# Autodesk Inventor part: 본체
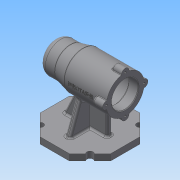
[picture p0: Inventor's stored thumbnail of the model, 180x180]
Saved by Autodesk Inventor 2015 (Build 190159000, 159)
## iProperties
Created: 2019-12
Part Number: 본체
Material: 일반
Document SubType Name: Modeling
Designer: user
Density: 1 g/cm^3
Appearance: 기본값
Mass: 268.496 g
Surface Area: 715.535 cm^2
Volume: 268.496 cm^3
Author: user
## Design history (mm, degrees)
sketch "스케치1"
  geometry: L1 (-56, 0)-(56, 0); L2 (56, 0)-(56, 21); L3 (56, 21)-(41, 21); L4 (41, 21)-(41, 24); L5 (41, 24)-(-13, 24); L6 (-13, 24)-(-13, 21); L7 (-13, 21)-(-25, 21); L8 (-25, 21)-(-25, 17.5); L9 (-25, 17.5)-(-43, 17.5); L10 (-43, 17.5)-(-43, 16); L11 (-43, 16)-(-47, 16); L12 (-47, 16)-(-47, 10.5); L13 (-47, 10.5)-(-50, 10.5); L14 (-50, 10.5)-(-50, 0); L15 (-56, 0)-(-56, 25); L16 (56, 21)-(56, 30); L17 (-56, 25)-(-31, 25); L18 (-31, 25)-(-11, 30); L19 (-11, 30)-(56, 30); 2 further points
  constraints: 38 end point, 10 perpendicular, 4 vertical, 3 point on line, 2 horizontal, 1 coincident, 1 midpoint
  dimensions: "d1" = 112 distance of L1.start L1.end; "d2" = 42 diameter of L3 L1; "d3" = 48 diameter of L5 L1; "d4" = 35 diameter of L9 L1; "d5" = 32 diameter of L11 L1; "d6" = 21 diameter of L13 L1; "d7" = 15 distance of L2.end L3.end; "d8" = 54 distance of L4.end L5.end; "d9" = 12 distance of L6.end L7.end; "d10" = 18 distance of L8.end L9.end; "d11" = 4 distance of L10.end L11.end; "d12" = 3 distance of L12.end L13.end; "d13" = 50 diameter of L15.end L1; "d14" = 60 diameter of L16.end L1; "d18" = 60 diameter of L18.end L1; "d19" = 25 distance of L15.end L17.end; "d20" = 45 horizontal distance of L18.end L15.end
revolve "회전1" sketch "스케치1" stored, may be unused: angle "d21" = 90 deg
fillet "모깎기1" dims "d22" = 3
fillet "모깎기2" dims "d23" = 3
chamfer "모따기1" distance "d24" = 1; stored, may be unused: second distance "d25" = 2, angle "d26" = 45 deg
sketch "스케치2"
  geometry: A1 r 6 centre (-30, 0) between (-29.4, 5.97) and (-29.4, -5.97); A2 r 6 centre (0, -30) between (-5.97, -29.4) and (5.97, -29.4); A3 r 6 centre (0, 30) between (5.97, 29.4) and (-5.97, 29.4); A4 r 6 centre (30, 0) between (29.4, -5.97) and (29.4, 5.97); 1 further point
  constraints: 8 point on circle, 4 centre point, 13 other
  dimensions: "d33" = 6 radius of A1; "d34" = 6 radius of A2; "d35" = 6 radius of A4; "d36" = 6 radius of A3; "d37" = 60 distance of A3.centre A2.centre; "d38" = 60 distance of A1.centre A4.centre; "d39" = 30 horizontal distance of A1.centre A3.centre; "d40" = 30 horizontal distance of A1.centre A2.centre
extrude "돌출1" join sketch "스케치2" distance "d41" = 16; taper "d42" = 0 deg
node "작업 평면1"
sketch "스케치5"
  geometry: A1 r 6 centre (0, 0) between (0.6, 5.97) and (0.6, -5.97) reference; A2 r 6 centre (30, -30) between (24.03, -29.4) and (35.97, -29.4) reference; A3 r 6 centre (60, 0) between (59.4, -5.97) and (59.4, 5.97) reference; A4 r 6 centre (30, 30) between (35.97, 29.4) and (24.03, 29.4) reference; 4 further points
  constraints: 4 coincident
hole "구멍1" sketch "스케치5" at (0, 0), (30, -30), (30, 30), (60, 0) diameter "d52" = 3.242; stored, may be unused: countersink angle "d56" = 90 deg, drill point angle "d58" = 118 deg; dims "d53" = 8, "d54" = 4, "d55" = 2, "d57" = 11
sketch "스케치6" dims "d60" = 112
  geometry: L1 (23.196, 56)-(56, 23.196); L2 (56, 23.196)-(56, -23.196); L3 (56, -23.196)-(23.196, -56); L4 (23.196, -56)-(-23.196, -56); L5 (-23.196, -56)-(-56, -23.196); L6 (-56, -23.196)-(-56, 23.196); L7 (-56, 23.196)-(-23.196, 56); L8 (-23.196, 56)-(23.196, 56); L9 (0, 0)-(0, 56); 3 further points
  constraints: 18 end point, 2 coincident, 2 midpoint, 1 vertical, 1 vertical alignment, 19 other
extrude "돌출3" join sketch "스케치6" distance "d61" = 10; taper "d62" = 0 deg
sketch "스케치8"
  geometry: L1 (-23.196, -70)-(-56, -70) reference; L2 (56, -70)-(23.196, -70) reference; L3 (36, -70)-(18.979, -23.234); L4 (-36, -70)-(-18.979, -23.234); L5 (-36, -70)-(36, -70); A1 r 30 centre (0, 0) between (18.979, -23.234) and (-18.979, -23.234) reference; A2 r 30 centre (0, 0) between (-18.979, -23.234) and (18.979, -23.234); 1 further point
  constraints: 6 end point, 4 point on circle, 2 point on line, 1 centre point, 1 coincident, 1 collinear, 1 concentric
  dimensions: "d68" = 110 deg angle of L2 L3; "d69" = 20 distance of L2.start L3.start; "d70" = 110 deg angle of L1 L4; "d71" = 20 distance of L1.end L4.start
extrude "돌출4" join sketch "스케치8" stored distance "d72" = 8; taper "d73" = 0 deg
sketch "스케치9"
  geometry: L1 (-56, -70)-(-23.196, -70) reference; L2 (11, -30)-(-40, -30) reference; L3 (31, -25)-(11, -30) reference; L4 (23.196, -70)-(56, -70) reference; L5 (38, -70)-(18.476, -28.131); L6 (-31, -70)-(-31, -30); 1 further point
  constraints: 4 end point, 4 point on line, 1 vertical
  dimensions: "d74" = 115 deg angle of L4 L5; "d75" = 18 distance of L4.end L5.start; "d76" = 25 distance from line of L1.start L6
feature "리브1" sketch "스케치9" dims "d77" = 1, "d78" = 8, "d79" = 0, "d80" = 0, "d81" = 1, "d82" = 1
sketch "스케치10"
  geometry: L1 (31, -25)-(11, -30) reference; L2 (23.196, -70)-(56, -70) reference; L3 (38, -70)-(18.476, -28.131); 1 further point
  constraints: 2 end point, 2 point on line
  dimensions: "d83" = 115 deg angle of L2 L3; "d84" = 18 distance of L2.end L3.start
feature "리브2" sketch "스케치10" dims "d85" = 1, "d86" = 8, "d87" = 0, "d88" = 0, "d89" = 1, "d90" = 1
fillet "모깎기4" dims "d94" = 10
sketch "스케치11"
  geometry: L1 (56, 23.196)-(23.196, 56) reference; L2 (-23.196, 56)-(-56, 23.196) reference; L3 (-56, -23.196)-(-23.196, -56) reference; L4 (23.196, -56)-(56, -23.196) reference; L5 (39.598, 39.598)-(-39.598, -39.598); L6 (-39.598, 39.598)-(39.598, -39.598); 5 further points
  constraints: 4 coincident, 4 end point, 4 midpoint
hole "구멍2" sketch "스케치11" at (-39.598, 39.598), (-39.598, -39.598), (39.598, -39.598), (39.598, 39.598) diameter "d95" = 10; stored, may be unused: countersink angle "d99" = 90 deg, drill point angle "d101" = 118 deg; dims "d96" = 8, "d97" = 4, "d98" = 2, "d100" = 11
fillet "모깎기6" dims "d103" = 3
fillet "모깎기7" dims "d104" = 1
fillet "모깎기8" dims "d105" = 3
fillet "모깎기9" dims "d106" = 3
fillet "모깎기10" dims "d107" = 3
fillet "모깎기12" dims "d112" = 3
fillet "모깎기13" dims "d114" = 0.3
node "작업 평면5"
sketch "스케치16"
  geometry: L1 (-56, 5.998)-(-56, -5.998) reference; L2 (10.631, 30)-(-39, 30) reference; 2 further points
  constraints: 1 other
  dimensions: "d119" = 41 distance from line of point (-15, 0) L1; "d120" = 30 distance from line of L2 point (-15, 0)
feature "엠보싱2" sketch "스케치16" dims "d1" = 112, "d2" = 42, "d3" = 48, "d4" = 35, "d5" = 32, "d6" = 21, "d7" = 15, "d8" = 54, "d9" = 12, "d10" = 18, "d11" = 4, "d12" = 3, "d13" = 50, "d14" = 60, "d18" = 60, "d19" = 25, "d20" = 45, "d121" = 0.5, "d122" = 0
node "솔리드1"
